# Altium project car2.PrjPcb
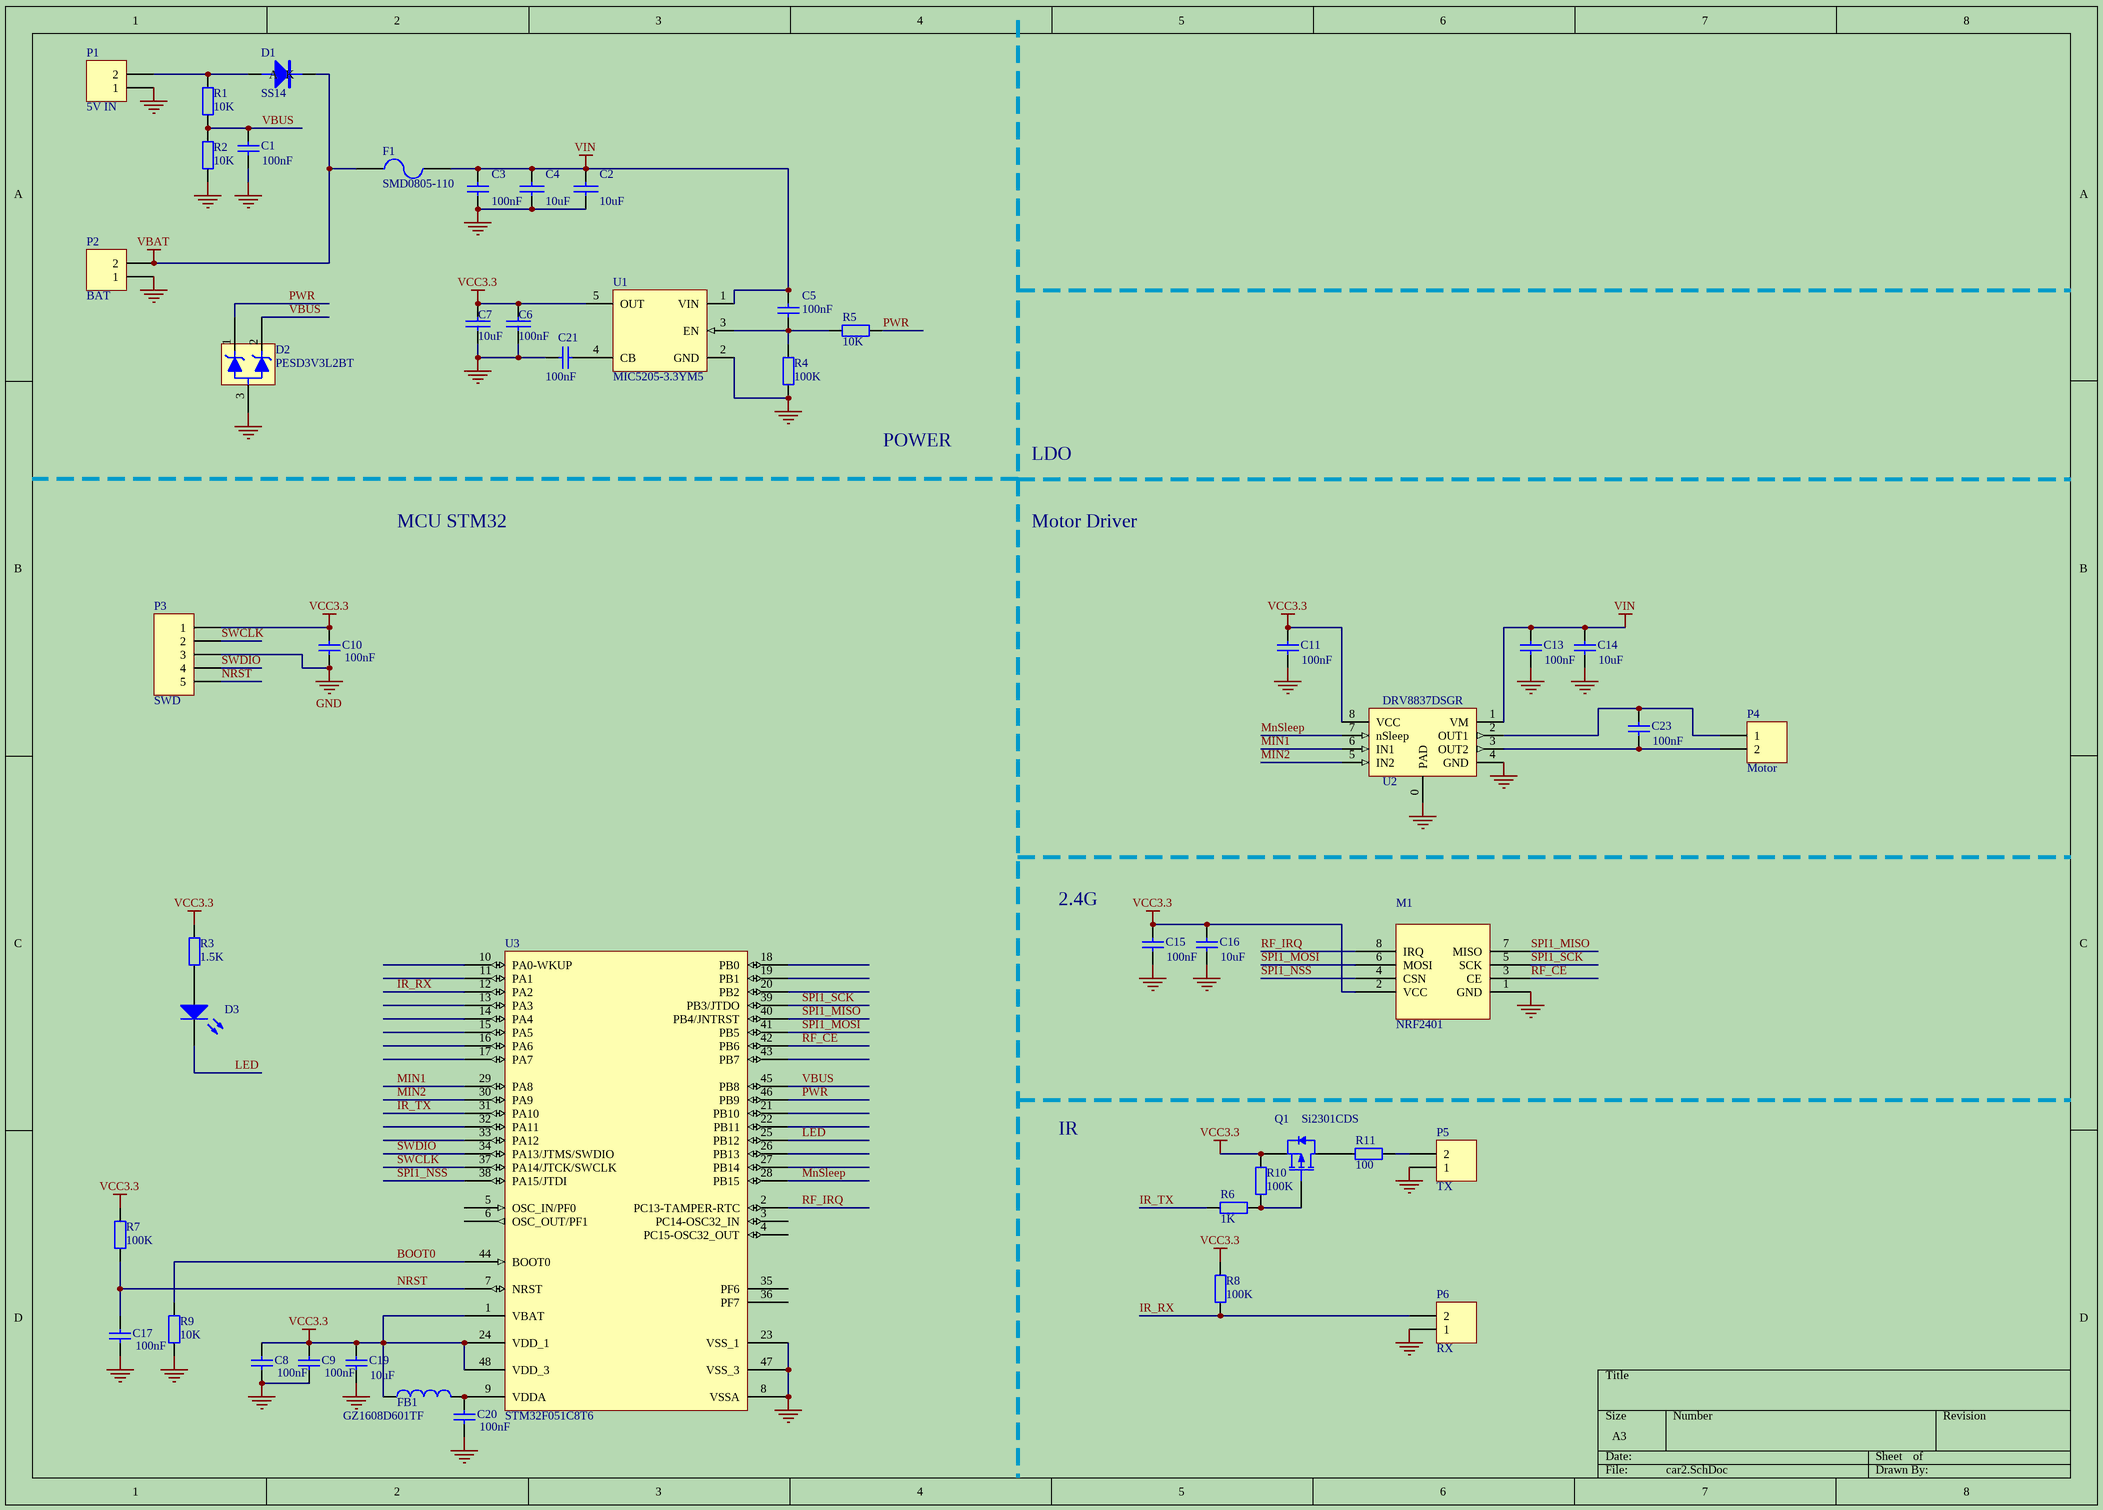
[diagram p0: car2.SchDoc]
1 sheet, 47 parts. Net scope: global (net labels, ports and power ports of the same name join across sheets).
Board files: CAR2.PcbDoc, IR.PcbDoc

## Sheet car2.SchDoc
size A3; SheetNumber: 0; SheetTotal: 0; PageSetup: Record=PageOptions¦CenterHorizontal=True¦CenterVertical=True¦PrintScale=0.73¦XCorrection=1.00¦YCorrection=1.00¦PrintKind=2¦BorderSize=5000000¦LeftOffset=0¦BottomOffset=0¦Orientation=2¦PaperLength=1000¦PaperWidth=1000¦Scale=100¦PaperSource=7¦PrintQuality=-4¦MediaType=1¦DitherType=10¦PaperKind=A4¦PrintScaleMode=1

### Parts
C1  100nF  [C0603]
C2  10uF  [C0805]
C3  100nF  [C0603]
C4  10uF  [C0805]
C5  100nF  [C0603]
C6  100nF  [C0603]
C7  10uF  [C0805]
C8  100nF  [C0603]
C9  100nF  [C0603]
C10  100nF  [C0603]
C11  100nF  [C0603]
C13  100nF  [C0603]
C14  10uF  [C0805]
C15  100nF  [C0603]
C16  10uF  [C0805]
C17  100nF  [C0603]
C19  10uF  [C0805]
C20  100nF  [C0603]
C21  100nF  [C0603]
C23  100nF  [C0603]
D1  SS14  [LC-SMA(DO-214AC)_S2]
D2  PESD3V3L2BT  [LC-SOT-23(SOT-23-3)]
D3  LEDV1  [LC-0603_LED_S4]  (value not drawn)
F1  SMD0805-110  [R0805]
FB1  GZ1608D601TF  [R0603]
M1  NRF2401  [HDR2X4]
P1  5V IN  [PH-2Y]
P2  BAT  [PH-2Y]
P3  SWD  [HDR1X5]
P4  Motor  [PH-2Y]
P5  TX  [PH-2Y]
P6  RX  [PH-2Y]
Q1  Si2301CDS  [LC-SOT-23(SOT-23-3)]
R1  10K  [R0603]
R2  10K  [R0603]
R3  1.5K  [R0603]
R4  100K  [R0603]
R5  10K  [R0603]
R6  1K  [R0603]
R7  100K  [R0603]
R8  100K  [R0603]
R9  10K  [R0603]
R10  100K  [R0603]
R11  100  [R0603]
U1  MIC5205-3.3YM5  [LC-SOT-23-5]
U2  DRV8837DSGR  [LC-WSON-8_2x2mm - DRV8837]
U3  STM32F051C8T6  [LC-LQFP-48_7x7x05P]

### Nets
GND: C1.1 C2.2 C3.1 C4.2 C6.2 C7.2 C8.1 C9.1 C10.2 C11.1 C13.1 C14.1 C15.1 C16.1 C17.1 C19.1 C20.1 C21.2 D2.3 M1.1(GND) P1.1 P2.1 P3.3 P5.1 P6.1 R2.1 R4.1 R9.1 U1.2(GND) U2.0(PAD) U2.4(GND) U3.8(VSSA) U3.23(VSS_1) U3.47(VSS_3)
VBAT: D1.2(K) F1.1 P2.2
VCC3.3: C6.1 C7.1 C8.2 C9.2 C10.1 C11.2 C15.2 C16.2 C19.2 FB1.1 M1.2(VCC) P3.1 Q1.2(S) R3.2 R7.2 R8.1 R10.1 U1.5(OUT) U2.8(VCC) U3.1(VBAT) U3.24(VDD_1) U3.48(VDD_3)
VIN: C2.1 C3.2 C4.1 C5.2 C13.2 C14.2 F1.2 U1.1(VIN) U2.1(VM)
BOOT0: R9.2 U3.44(BOOT0)
IR_RX: P6.2 R8.2 U3.12(PA2)
IR_TX: R6.2 U3.31(PA10)
LED: D3.K U3.25(PB12)
MIN1: U2.6(IN1) U3.29(PA8)
MIN2: U2.5(IN2) U3.30(PA9)
MnSleep: U2.7(nSleep) U3.28(PB15)
NRST: C17.2 P3.5 R7.1 U3.7(NRST)
PWR: D2.1 R5.1 U3.46(PB9)
RF_CE: M1.3(CE) U3.42(PB6)
RF_IRQ: M1.8(IRQ) U3.2(PC13-TAMPER-RTC)
SPI1_MISO: M1.7(MISO) U3.40(PB4/JNTRST)
SPI1_MOSI: M1.6(MOSI) U3.41(PB5)
SPI1_NSS: M1.4(CSN) U3.38(PA15/JTDI)
SPI1_SCK: M1.5(SCK) U3.39(PB3/JTDO)
SWCLK: P3.2 U3.37(PA14/JTCK/SWCLK)
SWDIO: P3.4 U3.34(PA13/JTMS/SWDIO)
VBUS: C1.2 D2.2 R1.1 R2.2 U3.45(PB8)
NetC5_1: C5.1 R4.2 R5.2 U1.3(EN)
NetC20_2: C20.2 FB1.2 U3.9(VDDA)
NetC21_1: C21.1 U1.4(CB)
NetC23_1: C23.1 P4.2 U2.3(OUT2)
NetC23_2: C23.2 P4.1 U2.2(OUT1)
NetD1_1: D1.1(A) P1.2 R1.2
NetD3_A: D3.A R3.1
NetP5_2: P5.2 R11.2
NetQ1_1: Q1.1(G) R6.1 R10.2
NetQ1_3: Q1.3(D) R11.1

Not connected (* = marked no-connect by the designer): U3 3(PC14-OSC32_IN) 4(PC15-OSC32_OUT) 5(OSC_IN/PF0) 6(OSC_OUT/PF1) 10(PA0-WKUP) 11(PA1) 13(PA3) 14(PA4) 15(PA5) 16(PA6) 17(PA7) 18(PB0) 19(PB1) 20(PB2) 21(PB10) 22(PB11) 26(PB13) 27(PB14) 32(PA11) 33(PA12) 35(PF6) 36(PF7) 43(PB7)

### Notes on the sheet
- POWER
- LDO
- MCU STM32
- Motor Driver
- 2.4G
- IR

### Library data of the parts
C1 C3 C5 C11 C13-C16 C19 C23 = Cap: Capacitor; Value: 10uF/10V
C2 C4 C6 C7 = CAP: Capacitor
C8-C10 C17 C20 = Cap: Capacitor
C21 = Cap: Capacitor; Value: 100pF
D1 = DIODE
D2 = ZENER2: TVS
D3 = LED2: Typical RED, GREEN, YELLOW, AMBER GaAs LED
F1 = Fuse 2: Fuse
FB1 = INDUCTOR1
P1 P2 P4-P6 = Header 2: Header, 2-Pin
P3 = Header 5: Header, 5-Pin
Q1 = BSH201: P-channel Enhancement Mode MOSFET
R1-R5 = Res2: Resistor; Value: 1K
R6 R8 R10 R11 = Res2: Resistor; Value: 10K
R7 R9 = Res2: Resistor
U1 = MIC5205: 150mA Low-Noise LDO Regulator
U2 = DRV883x: Low-Voltage H-Bridge Driver
U3 = STM32F51C8T6: STM32 ARM-based 32-bit MCU with 64 Kbytes Flash, 48-pin LQFP, Industrial Temperature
